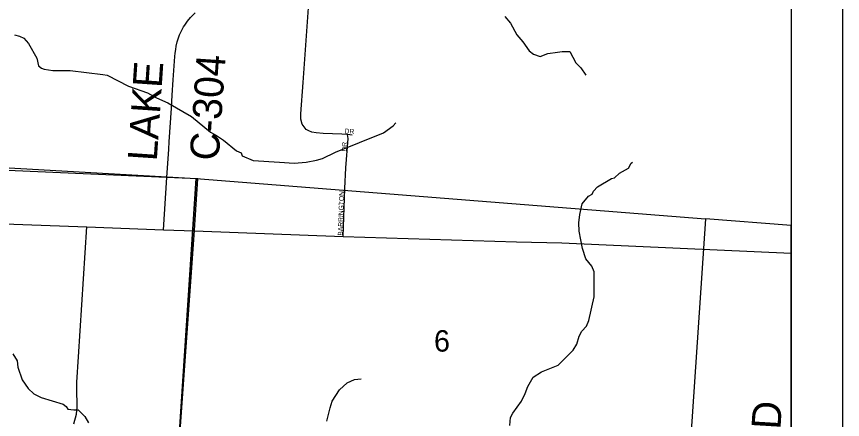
# Model space of a CAD drawing. Extents: x 0 to 40.4, y 0 to 22.
# Drawn here: x 7.886 to 9.5, y 16.72 to 17.508 of the extents above; entities that cross this region are included whole.
import ezdxf

# ---------------------------------------------------------------- set-up
doc = ezdxf.new("R2010")
doc.units = 0
for name, color, linetype in [('GM_X_County_Road', 7, 'Continuous'), ('GM_X_County_Road_Text', 7, 'Continuous'), ('GM_X_Minor_River', 7, 'Continuous'), ('GM_X_Section', 7, 'Continuous'), ('GM_X_Section_Text', 7, 'Continuous'), ('GM_X_Township', 7, 'Continuous'), ('GM_X_Township_Subdivision', 7, 'Continuous'), ('GM_X_Township_Subdivision_Text', 7, 'Continuous'), ('GM_X_US_Route', 7, 'Continuous'), ('SH_Data', 7, 'Continuous')]:
    doc.layers.add(name, color=color, linetype=linetype)

msp = doc.modelspace()

# ---------------------------------------------------------------- linework, layer by layer
at = {"layer": 'GM_X_County_Road'}
for points in [[(8.184, 17.2489), (8.185, 17.263), (8.1891, 17.3289), (8.1908, 17.3547), (8.1926, 17.3846), (8.1958, 17.4303), (8.1965, 17.4368), (8.1974, 17.4438), (8.1986, 17.4504), (8.2005, 17.4584), (8.2023, 17.4644), (8.2051, 17.4725), (8.2078, 17.4786), (8.2104, 17.484), (8.2128, 17.4878), (8.2152, 17.4913), (8.2207, 17.4991), (8.2263, 17.506), (8.2352, 17.5156)], [(8.1738, 17.0912), (8.1802, 17.1936), (8.184, 17.2489)], [(7.9986, 16.7119), (8.0034, 16.7309), (8.0048, 16.7445), (8.0043, 16.7815), (8.0046, 16.7931), (8.0078, 16.8426), (8.0237, 17.0971)]]:
    msp.add_lwpolyline(points, dxfattribs=at)
at = {"layer": 'GM_X_Minor_River'}
for points in [[(8.8407, 17.5085), (8.8516, 17.4949), (8.8637, 17.4725), (8.8758, 17.4588), (8.8878, 17.4413), (8.8965, 17.4349), (8.9097, 17.4303), (8.9241, 17.436), (8.9434, 17.4386), (8.9521, 17.4397), (8.9672, 17.44), (8.9793, 17.4177), (8.9891, 17.4078), (8.9989, 17.3937)], [(7.8825, 17.4721), (7.8924, 17.4701), (7.901, 17.466), (7.9097, 17.4557), (7.9263, 17.4265), (7.9293, 17.4121), (7.9353, 17.4075), (7.9402, 17.4052), (7.9572, 17.4029), (7.9913, 17.4025), (8.0552, 17.3948), (8.0635, 17.3936), (8.105, 17.3723), (8.1424, 17.359), (8.1602, 17.3491), (8.1821, 17.3392), (8.2285, 17.3129), (8.2652, 17.2818), (8.2727, 17.2783), (8.2788, 17.2741), (8.2905, 17.2665), (8.3165, 17.2456), (8.3256, 17.2418), (8.3275, 17.2358), (8.349, 17.227), (8.4004, 17.2231), (8.4287, 17.2212), (8.4522, 17.2234), (8.4726, 17.2271), (8.4843, 17.2309), (8.5093, 17.243), (8.6036, 17.2811), (8.6221, 17.2943), (8.6274, 17.3004)], [(8.8504, 16.7085), (8.8516, 16.724), (8.8562, 16.7327), (8.8728, 16.7558), (8.8801, 16.771), (8.8854, 16.785), (8.896, 16.8028), (8.9123, 16.8134), (8.9448, 16.8266), (8.9736, 16.8557), (8.9808, 16.8675), (8.9854, 16.883), (8.9907, 16.8929), (9.0002, 16.9027), (9.0044, 16.9141), (9.0147, 16.9603), (9.0147, 16.991), (9.0147, 17.0005), (9.0151, 17.0092), (9.0106, 17.0199), (8.9989, 17.0347), (8.9918, 17.0548), (8.9854, 17.0882), (8.9851, 17.1045), (8.987, 17.1208), (8.9916, 17.142), (9.0037, 17.1567), (9.0113, 17.1609), (9.0136, 17.167), (9.0215, 17.1749), (9.0491, 17.1915), (9.0548, 17.1927), (9.0643, 17.2018), (9.0817, 17.212), (9.0874, 17.2214), (9.0897, 17.2237)], [(7.879, 16.8484), (7.8877, 16.8347), (7.8888, 16.8229), (7.8974, 16.7975), (7.9095, 16.7812), (7.9201, 16.7702), (7.9344, 16.7633), (7.9775, 16.75), (7.9835, 16.7454), (7.9866, 16.7405), (7.9987, 16.7393), (8.007, 16.7393), (8.0202, 16.7264), (8.027, 16.7138)], [(8.4924, 16.7167), (8.4989, 16.7433), (8.5034, 16.7558), (8.5175, 16.7785), (8.5323, 16.7921), (8.547, 16.7985), (8.5595, 16.7997)]]:
    msp.add_lwpolyline(points, dxfattribs=at)
at = {"layer": 'GM_X_Section'}
msp.add_line((9.4, 16.5646), (9.4, 17.0997), dxfattribs=at)
for points in [[(7.3378, 17.2417), (7.7228, 17.2207), (8.2373, 17.1912), (8.202, 16.6562), (8.1953, 16.5941), (7.7054, 16.6198), (7.2909, 16.6427)], [(8.2373, 17.1912), (9.2326, 17.1127), (9.1966, 16.5816), (8.7372, 16.616), (8.202, 16.6562)]]:
    msp.add_lwpolyline(points, close=True, dxfattribs=at)
msp.add_lwpolyline([(9.4, 17.0997), (9.2326, 17.1127), (9.1966, 16.5816), (9.4, 16.5646)], dxfattribs=at)
at = {"layer": 'GM_X_Township'}
msp.add_lwpolyline([(8.0846, 14.9692), (8.096, 15.1213), (8.108, 15.2741), (8.1112, 15.3285), (8.1141, 15.384), (8.1155, 15.405), (8.1199, 15.4715), (8.1241, 15.5213), (8.1269, 15.5514), (8.127, 15.57), (8.1633, 16.0818), (8.1652, 16.1082), (8.2004, 16.6154), (8.2342, 17.0906), (8.241, 17.1909), (8.1794, 17.1936), (7.7202, 17.2134)], dxfattribs=at)
at = {"layer": 'GM_X_Township_Subdivision'}
for points in [[(8.5424, 17.2763), (8.5332, 17.2776), (8.5221, 17.2779), (8.4856, 17.2794), (8.4716, 17.2806), (8.4634, 17.282), (8.4574, 17.2844), (8.452, 17.2874), (8.4444, 17.2978), (8.4416, 17.3078), (8.4421, 17.3182), (8.4466, 17.379), (8.4584, 17.5441), (8.4624, 17.5953), (8.4608, 17.6121), (8.4583, 17.6179), (8.4548, 17.6233), (8.4485, 17.6293), (8.3949, 17.6757)], [(8.5244, 17.0778), (8.528, 17.1722), (8.5296, 17.2126), (8.5341, 17.2697), (8.5332, 17.2776)]]:
    msp.add_lwpolyline(points, dxfattribs=at)
at = {"layer": 'GM_X_US_Route'}
msp.add_lwpolyline([(7.7663, 17.1062), (7.773, 17.1059), (8.0237, 17.0971), (8.1738, 17.0912), (8.2341, 17.089), (8.5244, 17.0778), (8.8632, 17.0678), (8.9515, 17.0658), (9.4, 17.0454)], dxfattribs=at)
at = {"layer": 'SH_Data'}
for p, q in [((9.5, 21), (9.5, 14)), ((9.4, 20.9), (9.4, 14.1))]:
    msp.add_line(p, q, dxfattribs=at)

# ---------------------------------------------------------------- texts
at = {"layer": 'GM_X_County_Road_Text'}
for s, rotation, p in [('C-304', 86.1858, (8.2813, 17.2253)), ('LAKE', 86.1689, (8.1604, 17.2245)), ('RD', 86.5467, (9.3755, 16.6451))]:
    msp.add_text(s, height=0.05682, rotation=rotation, dxfattribs=at).set_placement(p)
at = {"layer": 'GM_X_Section_Text'}
msp.add_text('6', height=0.0419, rotation=0, dxfattribs=at).set_placement((8.702, 16.853))
at = {"layer": 'GM_X_Township_Subdivision_Text'}
for s, rotation, p in [('DR', 356.989, (8.5271, 17.2797)), ('DR', 86.989, (8.531, 17.2438)), ('BARRINGTON', 88.1128, (8.5235, 17.0796))]:
    msp.add_text(s, height=0.00947, rotation=rotation, dxfattribs=at).set_placement(p)

doc.saveas('drawing.dxf')
